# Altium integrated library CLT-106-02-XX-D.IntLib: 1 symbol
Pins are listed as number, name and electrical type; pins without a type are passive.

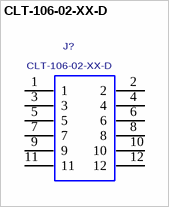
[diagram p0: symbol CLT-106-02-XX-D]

## CLT-106-02-XX-D
designator J?
LOW PROFILE SOCKET STRIP, 2mm PITCH, 12 PINS.; MANUFACTURER: SAMTEC
footprint CLT-106-02-XX-D
pins: 1, 2, 3, 4, 5, 6, 7, 8, 9, 10, 11, 12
